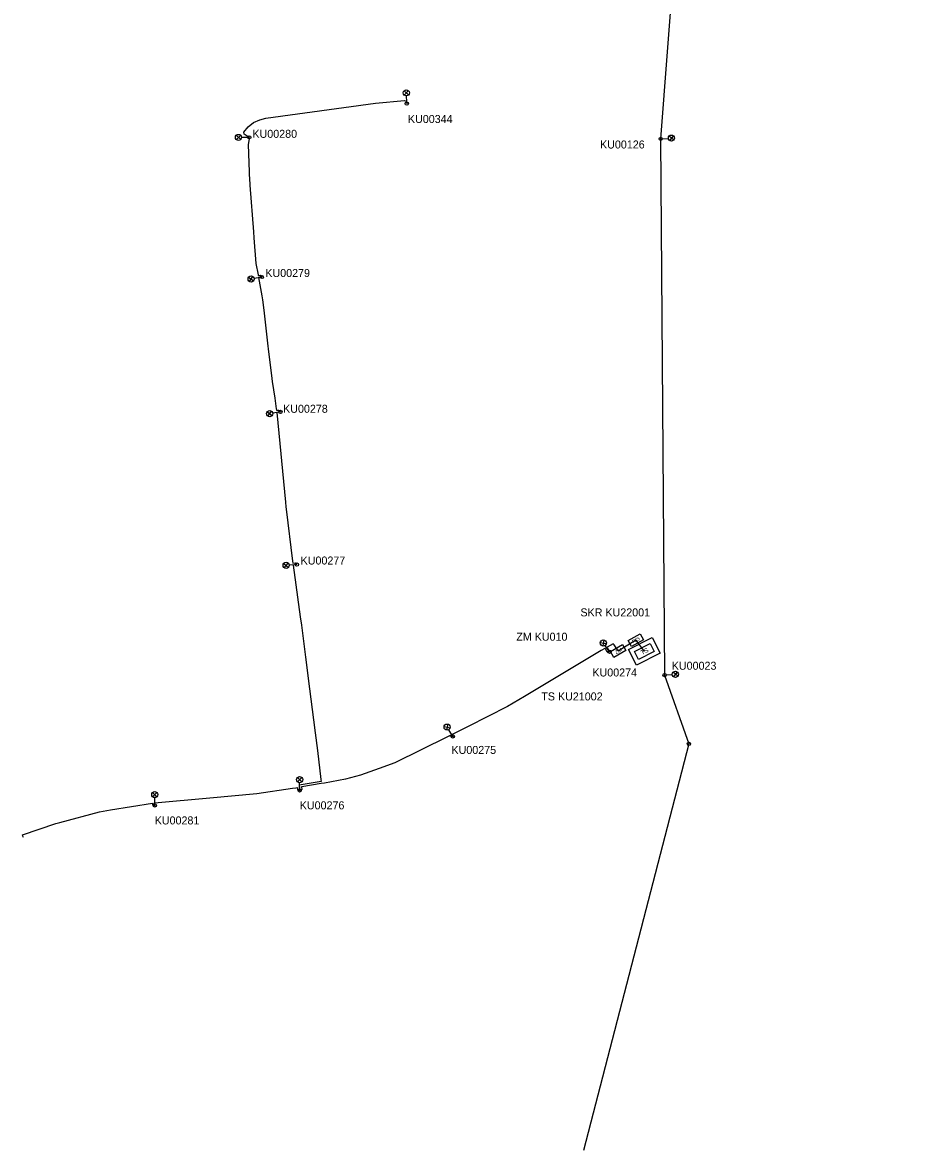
# Model space of a CAD drawing. Extents: x -727894 to -727647, y -1062988 to -1062565.
# Drawn here: x -727893.9 to -727725.3, y -1062988.2 to -1062776.8 of the extents above; entities that cross this region are included whole.
import ezdxf

# ---------------------------------------------------------------- set-up
doc = ezdxf.new("R2010")
doc.units = 0
for name, color, linetype in [('Kabelove_vedeni_vrchni', 7, 'Continuous'), ('Kabelove_vedeni_zemni', 7, 'Continuous'), ('Napajeci_kabel', 7, 'Continuous'), ('Pomocny_stozar', 7, 'Continuous'), ('RIS', 7, 'Continuous'), ('RIS_popis', 7, 'Continuous'), ('Trafostanice', 7, 'Continuous'), ('Trafostanice_popis', 7, 'Continuous'), ('Verejne_osvetleni', 7, 'Continuous'), ('Verejne_osvetleni_popis', 7, 'Continuous'), ('Zapinaci_misto', 7, 'Continuous'), ('Zapinaci_misto_popis', 7, 'Continuous')]:
    doc.layers.add(name, color=color, linetype=linetype)

msp = doc.modelspace()

# ---------------------------------------------------------------- linework, layer by layer
at = {"layer": 'Kabelove_vedeni_vrchni'}
for points in [[(-727725.31, -1062565.44), (-727767.53, -1062709.38), (-727769.22, -1062730.91), (-727774.35, -1062798.61)], [(-727774.35, -1062798.61), (-727773.61, -1062899.11)], [(-727773.61, -1062899.11), (-727769.06, -1062912), (-727788.79, -1062988.2)]]:
    msp.add_lwpolyline(points, dxfattribs=at)
at = {"layer": 'Kabelove_vedeni_zemni'}
for points in [[(-727851.41, -1062798.33), (-727852.36, -1062797.75), (-727852.44, -1062797.36), (-727851.61, -1062796.37), (-727850.6, -1062795.58), (-727849.43, -1062795.04), (-727848.29, -1062794.76), (-727827.76, -1062791.9), (-727822.36, -1062791.43), (-727822.05, -1062791.58), (-727821.91, -1062792.01)], [(-727851.41, -1062798.33), (-727851.45, -1062798.63), (-727851.61, -1062799.66), (-727851.35, -1062806.57), (-727851.34, -1062806.69), (-727851.3, -1062807.27), (-727850.64, -1062816.06), (-727850.55, -1062817.15), (-727850.19, -1062821.99), (-727849.77, -1062824.07), (-727849.74, -1062824.22), (-727849.38, -1062824.16), (-727849.08, -1062824.51)], [(-727849.08, -1062824.51), (-727849.38, -1062824.56), (-727849.66, -1062824.61), (-727849.07, -1062828.05), (-727848.94, -1062828.78), (-727848.71, -1062830.75), (-727847.99, -1062836.91), (-727847.8, -1062838.5), (-727847.28, -1062842.99), (-727847.12, -1062844.06), (-727846.65, -1062847.22), (-727846.36, -1062849.23), (-727846.32, -1062849.48), (-727845.97, -1062849.44), (-727845.59, -1062849.79)], [(-727845.59, -1062849.79), (-727845.89, -1062849.83), (-727846.26, -1062849.88), (-727844.66, -1062866.71), (-727844.57, -1062867.58), (-727844.53, -1062868.02), (-727843.3, -1062877.76), (-727843.25, -1062878.12), (-727842.83, -1062878.06), (-727842.49, -1062878.41)], [(-727842.49, -1062878.41), (-727842.79, -1062878.46), (-727843.2, -1062878.52), (-727841.86, -1062888.21), (-727841.65, -1062889.74), (-727840.88, -1062895.78), (-727840.13, -1062901.71), (-727839.39, -1062907.51), (-727839.08, -1062909.91), (-727838.66, -1062913.23), (-727838.02, -1062918.65), (-727837.97, -1062919.05), (-727842.07, -1062919.73), (-727842.04, -1062920.13), (-727841.98, -1062920.74)], [(-727783.93, -1062894.75), (-727784.37, -1062894.79), (-727784.75, -1062894.09), (-727784.83, -1062894.14), (-727785.47, -1062894.53), (-727799.87, -1062903.11), (-727803.05, -1062905.01), (-727810.42, -1062908.75), (-727813.4, -1062910.27), (-727813.38, -1062910.32), (-727813.29, -1062910.6)], [(-727782.3, -1062894.62), (-727782.46, -1062894.35), (-727783.03, -1062893.42), (-727783.24, -1062893.28), (-727784.4, -1062893.89), (-727784.07, -1062894.49), (-727783.93, -1062894.75)], [(-727813.29, -1062910.6), (-727813.7, -1062910.63), (-727813.76, -1062910.44), (-727814.27, -1062910.7), (-727824.16, -1062915.55), (-727827.1, -1062916.62), (-727830.57, -1062917.89), (-727833.38, -1062918.61), (-727837.35, -1062919.34), (-727837.92, -1062919.45), (-727841.58, -1062920.05), (-727841.64, -1062920.06), (-727841.6, -1062920.54), (-727841.98, -1062920.74)], [(-727869.13, -1062923.54), (-727869.15, -1062923.24), (-727869.16, -1062923.07), (-727858.81, -1062922.11), (-727850.01, -1062921.3), (-727843.32, -1062920.32), (-727842.71, -1062920.23), (-727842.44, -1062920.19), (-727842.39, -1062920.63), (-727841.98, -1062920.74)], [(-727893.7, -1062929.57), (-727893.81, -1062929.29), (-727893.89, -1062929.08), (-727887.63, -1062926.92), (-727886.93, -1062926.73), (-727879.46, -1062924.72), (-727877.41, -1062924.39), (-727869.56, -1062923.13), (-727869.54, -1062923.42), (-727869.13, -1062923.54)]]:
    msp.add_lwpolyline(points, dxfattribs=at)
at = {"layer": 'Napajeci_kabel'}
for points in [[(-727779, -1062892.58), (-727782.3, -1062894.62)], [(-727779, -1062892.58), (-727777.41, -1062894.67)]]:
    msp.add_lwpolyline(points, dxfattribs=at)
at = {"layer": 'Pomocny_stozar'}
msp.add_circle((-727769.06, -1062912), 0.305, dxfattribs=at)
at = {"layer": 'RIS'}
msp.add_lwpolyline([(-727780.46, -1062892.65), (-727778.19, -1062891.38), (-727777.55, -1062892.51), (-727779.82, -1062893.78)], close=True, dxfattribs=at)
at = {"layer": 'Trafostanice'}
for points in [[(-727780.4, -1062894.31), (-727775.94, -1062892.05), (-727774.43, -1062895.02), (-727778.89, -1062897.28)], [(-727779.28, -1062894.68), (-727776.3, -1062893.17), (-727775.55, -1062894.66), (-727778.52, -1062896.16)]]:
    msp.add_lwpolyline(points, close=True, dxfattribs=at)
at = {"layer": 'Verejne_osvetleni'}
for p, q in [((-727822.42, -1062789.6), (-727821.58, -1062790.37)), ((-727821.61, -1062789.56), (-727822.39, -1062790.41)), ((-727821.92, -1062791.7), (-727821.97, -1062790.56)), ((-727853.85, -1062797.95), (-727853.03, -1062798.75)), ((-727853.84, -1062798.76), (-727853.03, -1062797.94)), ((-727851.72, -1062798.33), (-727852.86, -1062798.34)), ((-727774.04, -1062798.59), (-727772.9, -1062798.52)), ((-727771.89, -1062798.86), (-727772.76, -1062798.1)), ((-727771.95, -1062798.05), (-727772.7, -1062798.91)), ((-727851.55, -1062824.56), (-727850.6, -1062825.21)), ((-727851.39, -1062825.36), (-727850.75, -1062824.41)), ((-727849.38, -1062824.57), (-727850.51, -1062824.78)), ((-727848.06, -1062849.78), (-727847.13, -1062850.45)), ((-727847.93, -1062850.58), (-727847.25, -1062849.65)), ((-727845.89, -1062849.84), (-727847.02, -1062850.02)), ((-727844.94, -1062878.17), (-727844.08, -1062878.93)), ((-727844.89, -1062878.98), (-727844.13, -1062878.12)), ((-727842.8, -1062878.43), (-727843.94, -1062878.51)), ((-727785.66, -1062892.99), (-727784.53, -1062893.19)), ((-727785, -1062892.53), (-727785.19, -1062893.66)), ((-727784.11, -1062894.5), (-727784.77, -1062893.56)), ((-727771.22, -1062898.52), (-727771.96, -1062899.39)), ((-727773.31, -1062899.08), (-727772.16, -1062899)), ((-727771.16, -1062899.33), (-727772.02, -1062898.58)), ((-727814.91, -1062908.74), (-727813.79, -1062909.01)), ((-727814.22, -1062908.32), (-727814.48, -1062909.43)), ((-727813.45, -1062910.34), (-727814.05, -1062909.36)), ((-727842.39, -1062918.31), (-727841.57, -1062919.12)), ((-727841.57, -1062918.31), (-727842.39, -1062919.12)), ((-727841.98, -1062920.43), (-727841.98, -1062919.29)), ((-727869.54, -1062921.11), (-727868.72, -1062921.92)), ((-727868.72, -1062921.11), (-727869.54, -1062921.92)), ((-727869.13, -1062923.23), (-727869.13, -1062922.09))]:
    msp.add_line(p, q, dxfattribs=at)
for centre, radius in [((-727822, -1062789.99), 0.574), ((-727821.91, -1062792.01), 0.306), ((-727853.44, -1062798.35), 0.574), ((-727851.41, -1062798.33), 0.306), ((-727774.35, -1062798.61), 0.306), ((-727772.33, -1062798.48), 0.574), ((-727851.07, -1062824.89), 0.574), ((-727849.08, -1062824.51), 0.306), ((-727847.59, -1062850.11), 0.574), ((-727845.59, -1062849.79), 0.306), ((-727844.51, -1062878.55), 0.574), ((-727842.49, -1062878.41), 0.306), ((-727785.1, -1062893.09), 0.574), ((-727783.93, -1062894.75), 0.306), ((-727771.59, -1062898.96), 0.574), ((-727773.61, -1062899.11), 0.306), ((-727814.35, -1062908.87), 0.574), ((-727813.29, -1062910.6), 0.306), ((-727841.98, -1062918.71), 0.574), ((-727869.13, -1062921.51), 0.574), ((-727841.98, -1062920.74), 0.306), ((-727869.13, -1062923.54), 0.306)]:
    msp.add_circle(centre, radius, dxfattribs=at)
at = {"layer": 'Zapinaci_misto'}
msp.add_lwpolyline([(-727783.75, -1062894.71), (-727781.5, -1062893.41), (-727780.85, -1062894.53), (-727783.1, -1062895.83)], close=True, dxfattribs=at)

# ---------------------------------------------------------------- texts
at = {"layer": 'RIS'}
msp.add_text('RIS', height=0.65, rotation=29.2606, dxfattribs=at).set_placement((-727779.47, -1062893.18))
at = {"layer": 'RIS_popis'}
msp.add_text('SKR KU22001', height=1.5, dxfattribs=at).set_placement((-727789.38, -1062888.11))
at = {"layer": 'Trafostanice'}
msp.add_text('TS', height=0.833, rotation=26.8728, dxfattribs=at).set_placement((-727777.84, -1062895.35))
at = {"layer": 'Trafostanice_popis'}
msp.add_text('TS KU21002', height=1.5, dxfattribs=at).set_placement((-727796.71, -1062903.86))
at = {"layer": 'Verejne_osvetleni_popis'}
for s, p in [('KU00344', (-727821.7, -1062795.64)), ('KU00280', (-727850.83, -1062798.42)), ('KU00126', (-727785.71, -1062800.42)), ('KU00279', (-727848.41, -1062824.51)), ('KU00278', (-727845.08, -1062849.95)), ('KU00277', (-727841.8, -1062878.39)), ('KU00274', (-727787.14, -1062899.37)), ('KU00023', (-727772.27, -1062898.11)), ('KU00275', (-727813.54, -1062913.89)), ('KU00276', (-727841.96, -1062924.27)), ('KU00281', (-727869.13, -1062927.1))]:
    msp.add_text(s, height=1.5, dxfattribs=at).set_placement(p)
at = {"layer": 'Zapinaci_misto'}
msp.add_text('ZM', height=0.65, rotation=30.0945, dxfattribs=at).set_placement((-727782.63, -1062895.19))
at = {"layer": 'Zapinaci_misto_popis'}
msp.add_text('ZM KU010', height=1.5, dxfattribs=at).set_placement((-727801.4, -1062892.67))

doc.saveas('drawing.dxf')
